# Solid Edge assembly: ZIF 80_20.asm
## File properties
Title: Zylinder
Author: bmolnar
Template: iso metric assembly.asm
Last saved by: psaghy
Revision: 18
Application: Solid Edge
Username: bmolnar
Dokumentum tartalom típus: 1
Document Number: ZIF 80/20
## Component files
Kolbenstange.par
Kit_1.par
Kit_2.par
Profilrohr.par
Mutter.par
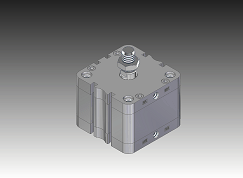
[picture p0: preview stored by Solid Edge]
